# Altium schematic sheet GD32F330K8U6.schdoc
size 127 x 101 mm
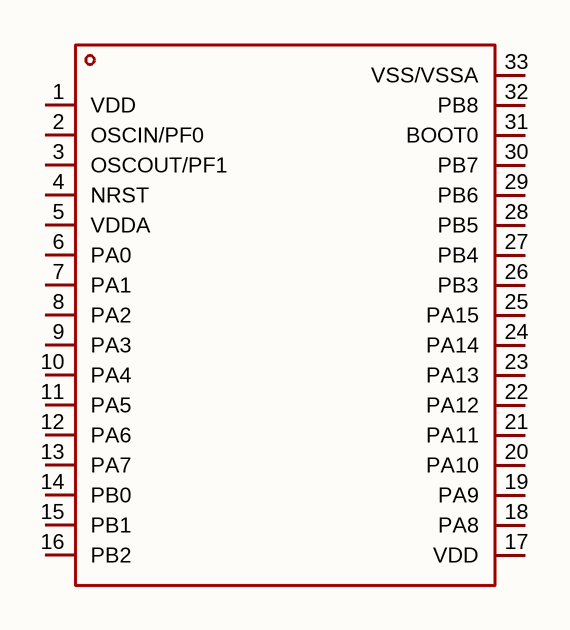
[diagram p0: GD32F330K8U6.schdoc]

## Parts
U?  gd32f330k8u6  [QFN-32_L5.0-W5.0-P0.50-TL-EP3.5]  (value not drawn)

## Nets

Not connected (* = marked no-connect by the designer): U? 1(VDD) 2(OSCIN/PF0) 3(OSCOUT/PF1) 4(NRST) 5(VDDA) 6(PA0) 7(PA1) 8(PA2) 9(PA3) 10(PA4) 11(PA5) 12(PA6) 13(PA7) 14(PB0) 15(PB1) 16(PB2) 17(VDD) 18(PA8) 19(PA9) 20(PA10) 21(PA11) 22(PA12) 23(PA13) 24(PA14) 25(PA15) 26(PB3) 27(PB4) 28(PB5) 29(PB6) 30(PB7) 31(BOOT0) 32(PB8) 33(VSS/VSSA)

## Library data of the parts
U? = gd32f330k8u6: CPU内核:ARM Cortex-M4;CPU最大主频:84MHz;CPU位数:32 Bit;; Manufacturer: GigaDevice(兆易创新); AddInBom: yes; ModelId: 876e8823170543eb9dee7bb925cd2b1b; ModelName: QFN-32_L5.0-W5.0-H1.0-P0.50-TL-EP3.5; ModelTransform: 196.85,196.85,0,0,0,0,0,0,0; CPU Maximum Speed: 84MHz; Core Size: 32 Bit; Program Storage Size: 64KB; Program Memory Type: FLASH; Number of I/O: 27; ADC (Bit): 12bit; Oscillator Type: 内置+外置; Voltage - Supply: 2.6V~3.6V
